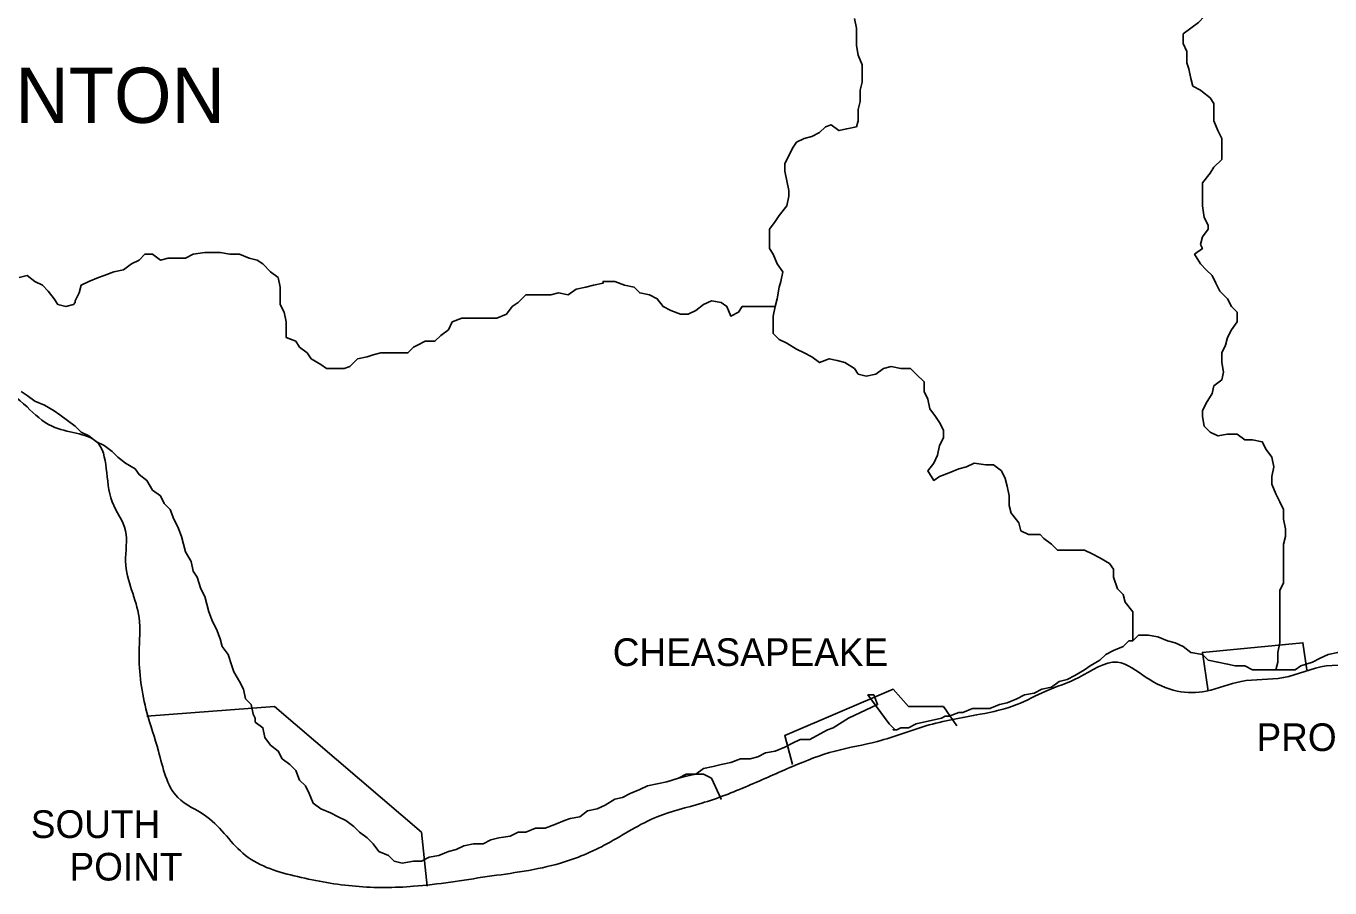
# Model space of a CAD drawing. Extents: x 0 to 34, y 0 to 22.
# Drawn here: x 7.373 to 8.293, y 14.971 to 15.579 of the extents above; entities that cross this region are included whole.
import ezdxf

# ---------------------------------------------------------------- set-up
doc = ezdxf.new("R2010")
doc.units = 0
doc.layers.add('Default', color=7, linetype='Continuous')

msp = doc.modelspace()

# ---------------------------------------------------------------- linework, layer by layer
at = {"layer": 'Default'}
for points in [[(8.20136, 15.53343), (8.19591, 15.53616), (8.19455, 15.54161), (8.19318, 15.54843), (8.19182, 15.55252), (8.19182, 15.5607), (8.18909, 15.56616), (8.18909, 15.57297), (8.19455, 15.57706), (8.2, 15.58115), (8.20409, 15.58524), (8.20682, 15.5907), (8.20273, 15.59615), (8.2, 15.60161), (8.19727, 15.60706), (8.19727, 15.61388), (8.19727, 15.61524), (8.19727, 15.6166)], [(7.93686, 15.50753), (7.94095, 15.50889), (7.9464, 15.5048), (7.95186, 15.50617), (7.95868, 15.50753), (7.96004, 15.51162), (7.96004, 15.5198), (7.9614, 15.52525), (7.9614, 15.53343), (7.96277, 15.53889), (7.96277, 15.5457), (7.96277, 15.55116), (7.96004, 15.55798), (7.95868, 15.56479), (7.95868, 15.57025), (7.95868, 15.57706), (7.95731, 15.58388)], [(8.21636, 15.49253), (8.21636, 15.49935), (8.21364, 15.5048), (8.21091, 15.51162), (8.21091, 15.51707), (8.21091, 15.52389), (8.20818, 15.52798), (8.20273, 15.53207), (8.20136, 15.53343)], [(7.91641, 15.49662), (7.92186, 15.49935), (7.92732, 15.50071), (7.93277, 15.50344), (7.93686, 15.50753)], [(7.91641, 15.49662), (7.92186, 15.49935), (7.92732, 15.50071), (7.93277, 15.50344), (7.93686, 15.50753)], [(7.90141, 15.38073), (7.90278, 15.38618), (7.90414, 15.39437), (7.9055, 15.39846), (7.90687, 15.40527), (7.90278, 15.41073), (7.90005, 15.41754), (7.89732, 15.42163), (7.89732, 15.42981), (7.89732, 15.43527), (7.90141, 15.44072), (7.90414, 15.44481), (7.90959, 15.45163), (7.91096, 15.45845), (7.91096, 15.46254), (7.90959, 15.46935), (7.90823, 15.47617), (7.90823, 15.48162), (7.91096, 15.48708), (7.91368, 15.49253), (7.91641, 15.49662), (7.91641, 15.49662)], [(8.20682, 15.43799), (8.20409, 15.44345), (8.20273, 15.45163), (8.20273, 15.45708), (8.20273, 15.46254), (8.20273, 15.46799), (8.20818, 15.47481), (8.21091, 15.4789), (8.21636, 15.48435), (8.21636, 15.49117), (8.21636, 15.49253)], [(8.20273, 15.30711), (8.20545, 15.31256), (8.20954, 15.31938), (8.21091, 15.32483), (8.21636, 15.32892), (8.21773, 15.33437), (8.21636, 15.34119), (8.21636, 15.34801), (8.21909, 15.35346), (8.22045, 15.35892), (8.22318, 15.36437), (8.22727, 15.36982), (8.22727, 15.37664), (8.22318, 15.38073), (8.22045, 15.38618), (8.215, 15.39164), (8.21227, 15.39709), (8.20954, 15.40255), (8.20545, 15.40664), (8.20136, 15.41073), (8.19727, 15.41754), (8.20273, 15.42163), (8.20136, 15.42436), (8.20273, 15.42981), (8.20682, 15.43527), (8.20682, 15.43799), (8.20682, 15.43799), (8.20682, 15.43799)], [(7.40785, 15.38482), (7.41058, 15.39027), (7.41194, 15.39573), (7.4174, 15.39846), (7.42421, 15.40118), (7.4283, 15.40255), (7.43512, 15.40527), (7.44194, 15.40664), (7.44739, 15.41073), (7.45285, 15.41345), (7.45694, 15.41754), (7.46239, 15.41754), (7.46784, 15.41345), (7.4733, 15.41482), (7.48011, 15.41482), (7.48557, 15.41482), (7.49102, 15.41754), (7.4992, 15.41891), (7.50466, 15.41891), (7.51011, 15.41891), (7.51693, 15.41754), (7.52374, 15.41754), (7.53056, 15.41482), (7.53602, 15.41345), (7.54011, 15.41073), (7.54556, 15.40527), (7.55101, 15.40118), (7.55101, 15.40118), (7.55101, 15.40118)], [(7.36831, 15.40118), (7.37377, 15.40255), (7.37922, 15.39846), (7.38468, 15.39573), (7.38877, 15.39164), (7.39286, 15.38618), (7.39558, 15.38209), (7.40104, 15.38073), (7.40649, 15.38209), (7.40785, 15.38346), (7.40785, 15.38482)], [(7.55101, 15.40118), (7.55238, 15.39437), (7.55238, 15.38891), (7.55238, 15.38209), (7.5551, 15.37664), (7.55647, 15.36982), (7.55647, 15.36437), (7.55647, 15.35892), (7.56328, 15.35619), (7.56601, 15.3521), (7.57146, 15.34801), (7.57419, 15.34392), (7.58101, 15.33983), (7.5851, 15.3371), (7.59192, 15.3371), (7.59737, 15.3371), (7.60146, 15.33846), (7.60146, 15.33846)], [(7.64918, 15.35346), (7.65463, 15.35619), (7.66145, 15.35619), (7.66554, 15.36028), (7.67099, 15.36437), (7.67372, 15.36982), (7.68054, 15.37255), (7.68735, 15.37255), (7.69281, 15.37255), (7.69826, 15.37255), (7.70508, 15.37255), (7.7119, 15.37528), (7.71599, 15.38073), (7.72008, 15.38346), (7.72553, 15.38891), (7.72962, 15.38891), (7.73644, 15.38891), (7.74326, 15.38891), (7.74871, 15.39027), (7.75553, 15.38891), (7.76098, 15.393), (7.7678, 15.39437), (7.77325, 15.39573), (7.78007, 15.39709), (7.78007, 15.39846), (7.78416, 15.39846)], [(7.78416, 15.39846), (7.78825, 15.39846), (7.79507, 15.39573), (7.80188, 15.39437), (7.80597, 15.39027), (7.81279, 15.38891), (7.81824, 15.38618), (7.82233, 15.38073), (7.82779, 15.378), (7.8346, 15.37528), (7.84006, 15.37528), (7.84551, 15.378), (7.85097, 15.38209), (7.85642, 15.38482), (7.86324, 15.38346), (7.86733, 15.38073), (7.87005, 15.37391), (7.87551, 15.37664), (7.87823, 15.38073), (7.88505, 15.38073), (7.89187, 15.38073), (7.89732, 15.38073), (7.90141, 15.38073)], [(7.90141, 15.38073), (7.90005, 15.37391), (7.90005, 15.36846), (7.90005, 15.36164), (7.90414, 15.35755), (7.90959, 15.35483), (7.91641, 15.35074), (7.92186, 15.34801), (7.92732, 15.34528), (7.93277, 15.34119), (7.93959, 15.34392), (7.94504, 15.34256), (7.95049, 15.34119), (7.95731, 15.3371)], [(7.60146, 15.33846), (7.60691, 15.34392), (7.61373, 15.34528), (7.61782, 15.34665), (7.62327, 15.34801), (7.63009, 15.34801), (7.63691, 15.34801), (7.64236, 15.34801), (7.64645, 15.3521), (7.64918, 15.35346)], [(7.95731, 15.3371), (7.96004, 15.33301), (7.96549, 15.33165), (7.97231, 15.33301), (7.97776, 15.3371), (7.98322, 15.33846), (7.99003, 15.3371), (7.99685, 15.3371), (8.00094, 15.33301), (8.0064, 15.32756), (8.0064, 15.32074), (8.00912, 15.31529), (8.01049, 15.30847), (8.01458, 15.30302), (8.0173, 15.29893), (8.02003, 15.29347), (8.02003, 15.28802), (8.0173, 15.28256), (8.01594, 15.27575), (8.01321, 15.27029), (8.00912, 15.26484), (8.01321, 15.25802), (8.0173, 15.26075), (8.02412, 15.26348), (8.03094, 15.2662), (8.03639, 15.26757), (8.04184, 15.27029), (8.05002, 15.26893), (8.05548, 15.26893), (8.06093, 15.26484), (8.06366, 15.25939), (8.06502, 15.25393), (8.06639, 15.24712), (8.06639, 15.2403), (8.06775, 15.23484), (8.06911, 15.23348)], [(7.36968, 15.32074), (7.37377, 15.31801), (7.37922, 15.31392), (7.38604, 15.3112), (7.39286, 15.30711), (7.39695, 15.30438), (7.4024, 15.30029), (7.40785, 15.2962), (7.41194, 15.29211), (7.4174, 15.28938), (7.42285, 15.28529), (7.4283, 15.28256), (7.43376, 15.27847), (7.43785, 15.27438), (7.4433, 15.27029), (7.45012, 15.2662), (7.45285, 15.26211), (7.4583, 15.25802), (7.46239, 15.25121), (7.46784, 15.24712), (7.47057, 15.24166), (7.47466, 15.23757), (7.47739, 15.23075), (7.48011, 15.2253), (7.48284, 15.21848), (7.48421, 15.21303), (7.48557, 15.20758), (7.48966, 15.20076), (7.49102, 15.19394), (7.49375, 15.18985), (7.49648, 15.18167), (7.4992, 15.17622), (7.50057, 15.17076), (7.50193, 15.16531), (7.50466, 15.15849), (7.50738, 15.15304), (7.51011, 15.14622), (7.51147, 15.14077), (7.51556, 15.13532), (7.51829, 15.12713), (7.51965, 15.12304), (7.52374, 15.11623), (7.52647, 15.11077), (7.52783, 15.10396), (7.53192, 15.09987), (7.53329, 15.09305), (7.53465, 15.09032), (7.53465, 15.0876)], [(8.26135, 15.22394), (8.25999, 15.23075), (8.25999, 15.23757), (8.25726, 15.24303), (8.25454, 15.24848), (8.25181, 15.2553), (8.25181, 15.26075), (8.25317, 15.26757), (8.25181, 15.27438), (8.24772, 15.27984), (8.24499, 15.28529), (8.23818, 15.28665), (8.23272, 15.28665), (8.22727, 15.29075), (8.22045, 15.29075), (8.21364, 15.28938), (8.20818, 15.29211), (8.20409, 15.2962), (8.20273, 15.30302), (8.20273, 15.30711)], [(8.06911, 15.23348), (8.0732, 15.22803), (8.07457, 15.22257), (8.08002, 15.21985), (8.0882, 15.21985), (8.09093, 15.21712), (8.09638, 15.21303), (8.10047, 15.20894), (8.10729, 15.20894), (8.11411, 15.20894), (8.11956, 15.20894), (8.12501, 15.20621), (8.13047, 15.20349), (8.13728, 15.1994), (8.14001, 15.19531), (8.14001, 15.18985), (8.14274, 15.18167), (8.14683, 15.17758), (8.14819, 15.17213), (8.15364, 15.16531), (8.15364, 15.15986), (8.15364, 15.1544), (8.15364, 15.14759), (8.15364, 15.14486)], [(8.25454, 15.12441), (8.2559, 15.12986), (8.2559, 15.13668), (8.25726, 15.1435), (8.25726, 15.14895), (8.25726, 15.15577), (8.25726, 15.16122), (8.25726, 15.16804), (8.25726, 15.17622), (8.25726, 15.18031), (8.25999, 15.18576), (8.25999, 15.19258), (8.25999, 15.1994), (8.25999, 15.20621), (8.25999, 15.21303), (8.26135, 15.21848), (8.26135, 15.22257), (8.26135, 15.22394)], [(8.15364, 15.14486), (8.15773, 15.14895), (8.16455, 15.14895), (8.17137, 15.14759), (8.17819, 15.14486), (8.18364, 15.1435), (8.18909, 15.14077), (8.19455, 15.13668), (8.20273, 15.13532), (8.20682, 15.13122), (8.21364, 15.12986), (8.22045, 15.1285), (8.22591, 15.12713), (8.23272, 15.12713), (8.23818, 15.12441), (8.24499, 15.12441), (8.25181, 15.12441), (8.25454, 15.12441), (8.25454, 15.12441)], [(8.15364, 15.14486), (8.15773, 15.14895), (8.16455, 15.14895), (8.17137, 15.14759), (8.17819, 15.14486), (8.18364, 15.1435), (8.18909, 15.14077), (8.19455, 15.13668), (8.20273, 15.13532), (8.20682, 15.13122), (8.21364, 15.12986), (8.22045, 15.1285), (8.22591, 15.12713), (8.23272, 15.12713), (8.23818, 15.12441), (8.24499, 15.12441), (8.25181, 15.12441), (8.25454, 15.12441), (8.25454, 15.12441)], [(7.98731, 15.08214), (7.99003, 15.08351), (7.99549, 15.08351), (8.00094, 15.08623), (8.01867, 15.09032), (8.02139, 15.09169), (8.02412, 15.09169), (8.03094, 15.09441), (8.03366, 15.09441), (8.04048, 15.09714), (8.0473, 15.09714), (8.05275, 15.09714), (8.05957, 15.09987), (8.06502, 15.10123), (8.07184, 15.10396), (8.07729, 15.10668), (8.08411, 15.10805), (8.08956, 15.11077), (8.09638, 15.11214), (8.10183, 15.11623), (8.10729, 15.11759), (8.11274, 15.12032), (8.11956, 15.12441), (8.12365, 15.12713), (8.13047, 15.13122), (8.13456, 15.13532), (8.14001, 15.13804), (8.14683, 15.14077), (8.15092, 15.14486), (8.15228, 15.14486), (8.15364, 15.14486)], [(8.20682, 15.10941), (8.20273, 15.13668), (8.27363, 15.1435), (8.27635, 15.12441)], [(8.25454, 15.12441), (8.26272, 15.12441), (8.26817, 15.12441), (8.27226, 15.12713), (8.28044, 15.12986), (8.2859, 15.13259), (8.29135, 15.13532), (8.29817, 15.13668), (8.30362, 15.13941), (8.30498, 15.13941)], [(8.25454, 15.12441), (8.26272, 15.12441), (8.26817, 15.12441), (8.27226, 15.12713), (8.28044, 15.12986), (8.2859, 15.13259), (8.29135, 15.13532), (8.29817, 15.13668), (8.30362, 15.13941), (8.30498, 15.13941)], [(7.91368, 15.0576), (7.90823, 15.07805), (7.98458, 15.11077), (7.99549, 15.0985), (8.02003, 15.0985), (8.02957, 15.08487)], [(7.83324, 15.04806), (7.83869, 15.05078), (7.84551, 15.05078), (7.85097, 15.05487), (7.85778, 15.05624), (7.86324, 15.0576), (7.87005, 15.05896), (7.87687, 15.06169), (7.88369, 15.06169), (7.88914, 15.06305), (7.89459, 15.06578), (7.90141, 15.06714), (7.90823, 15.06987), (7.91368, 15.0726), (7.91914, 15.07532), (7.92595, 15.07532), (7.93822, 15.08214), (7.94231, 15.08351), (7.95322, 15.09032), (7.97367, 15.09987), (7.97095, 15.10668), (7.96686, 15.10668), (7.98185, 15.08623), (7.98458, 15.08351), (7.98594, 15.08214), (7.98594, 15.08214), (7.98458, 15.08214), (7.98731, 15.08214)], [(7.4583, 15.09169), (7.54829, 15.0985), (7.65191, 15.00988), (7.656, 14.9717)], [(7.53465, 15.0876), (7.54011, 15.08351), (7.54147, 15.07669), (7.54556, 15.07123), (7.55101, 15.06714), (7.55374, 15.06169), (7.55919, 15.0576), (7.56328, 15.05351), (7.56601, 15.04669), (7.5701, 15.0426), (7.57283, 15.03715), (7.57555, 15.03033), (7.58101, 15.02624), (7.58783, 15.02351), (7.59328, 15.02079), (7.59873, 15.01806), (7.60419, 15.01397), (7.60828, 15.00988), (7.61373, 15.00579), (7.61782, 15.0017), (7.61782, 15.0017), (7.61782, 15.0017)], [(7.61782, 15.0017), (7.62191, 14.99625), (7.62873, 14.99352), (7.63282, 14.98943), (7.63827, 14.98807), (7.64645, 14.98943), (7.65191, 14.98943), (7.65736, 14.99216), (7.66418, 14.99352), (7.67099, 14.99625), (7.67645, 14.99761), (7.6819, 15.00034), (7.68872, 15.0017), (7.69554, 15.0017), (7.70099, 15.00443), (7.70644, 15.00579), (7.71462, 15.00715), (7.72008, 15.00988), (7.72553, 15.00988), (7.73235, 15.01261), (7.73916, 15.01261), (7.74598, 15.01533), (7.7528, 15.01806), (7.75689, 15.01942), (7.76371, 15.02079), (7.76916, 15.02488), (7.77598, 15.02624), (7.78143, 15.02897), (7.78825, 15.03306), (7.7937, 15.03442), (7.79916, 15.03715), (7.80597, 15.03988), (7.81143, 15.0426), (7.81824, 15.04397), (7.82506, 15.04533), (7.83324, 15.04806)], [(7.83324, 15.04806), (7.83869, 15.04942), (7.84551, 15.05078), (7.85097, 15.05078), (7.85642, 15.04806), (7.86324, 15.03306), (7.86324, 15.03306)]]:
    msp.add_lwpolyline(points, dxfattribs=at)
msp.add_spline([(8.57494, 15.78021), (8.55449, 15.75431), (8.54767, 15.72977), (8.55449, 15.69159), (8.54767, 15.67659), (8.54495, 15.64932), (8.53813, 15.62342), (8.53813, 15.60297), (8.53813, 15.57434), (8.53268, 15.55252), (8.52313, 15.53343), (8.51359, 15.50753), (8.51359, 15.47617), (8.51359, 15.43799), (8.51359, 15.40118), (8.50268, 15.37391), (8.49177, 15.33846), (8.48359, 15.30029), (8.48087, 15.27438), (8.47405, 15.24712), (8.45905, 15.2103), (8.44269, 15.17349), (8.42769, 15.15849), (8.39633, 15.14077), (8.36497, 15.13668), (8.32544, 15.12713), (8.28999, 15.12713), (8.25999, 15.11895), (8.23, 15.11623), (8.20545, 15.10941), (8.185, 15.10941), (8.16319, 15.11895), (8.14274, 15.12986), (8.11547, 15.11895), (8.09229, 15.10941), (8.07184, 15.09987), (8.04593, 15.09305), (8.00776, 15.08487), (7.97367, 15.07396), (7.94368, 15.06714), (7.91368, 15.05624), (7.88232, 15.0426), (7.8496, 15.03033), (7.81824, 15.02079), (7.78279, 15.0017), (7.75007, 14.98807), (7.69826, 14.97852), (7.64645, 14.9717), (7.60555, 14.9717), (7.56465, 14.97852), (7.52783, 14.99352), (7.50057, 15.02079), (7.48011, 15.03442), (7.46648, 15.06714), (7.4583, 15.09441), (7.45285, 15.13668), (7.45285, 15.16122), (7.4433, 15.20076), (7.4433, 15.22257), (7.43376, 15.24303), (7.42285, 15.28529), (7.39149, 15.2962), (7.37377, 15.30983), (7.33014, 15.33846), (7.29605, 15.3521), (7.26333, 15.38073), (7.23606, 15.423), (7.20061, 15.45845), (7.17198, 15.50071), (7.15835, 15.54025), (7.13653, 15.58252), (7.09836, 15.60297), (7.07382, 15.62751), (7.04246, 15.64932), (7.01382, 15.66569), (6.98928, 15.67659), (6.93884, 15.67659), (6.90748, 15.67659), (6.88566, 15.68068), (6.8543, 15.67659), (6.83385, 15.67659), (6.79022, 15.68068), (6.74796, 15.69159), (6.72478, 15.71204), (6.69478, 15.72431)], degree=3, dxfattribs=at)

# ---------------------------------------------------------------- texts
for s, height, p in [('IRONTON', 0.039005, (7.27287, 15.51026)), ('CHEASAPEAKE', 0.0195024, (7.78688, 15.12713)), ('PROCTORVILLE', 0.0195024, (8.2409, 15.06714)), ('SOUTH', 0.019502, (7.37649, 15.00579)), ('POINT', 0.019502, (7.40376, 14.97579))]:
    msp.add_text(s, height=height, dxfattribs=at).set_placement(p)

doc.saveas('drawing.dxf')
